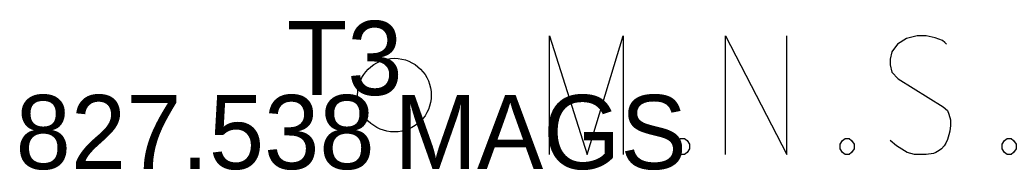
# Model space of a CAD drawing. Extents: x 1455931 to 1456172, y 560190 to 560355.
# Drawn here: x 1456075.1 to 1456088.52, y 560315.32 to 560317.35 of the extents above; entities that cross this region are included whole.
import ezdxf

# ---------------------------------------------------------------- set-up
doc = ezdxf.new("R2010")
doc.units = 0
for name, color, linetype in [('SV_P_Control_Cells_Set', 7, 'Continuous'), ('SV_X_Text_Comment', 7, 'Continuous'), ('SV_X_Text_Elevation', 7, 'Continuous'), ('SV_X_Text_Name', 7, 'Continuous')]:
    doc.layers.add(name, color=color, linetype=linetype)

msp = doc.modelspace()

# ---------------------------------------------------------------- linework, layer by layer
at = {"layer": 'SV_P_Control_Cells_Set'}
for points in [[(1456082.234, 560315.531), (1456082.234, 560317.131), (1456082.741, 560315.531), (1456083.226, 560317.131), (1456083.226, 560315.531)], [(1456084.604, 560315.531), (1456084.604, 560317.131), (1456085.431, 560315.531), (1456085.431, 560317.131)], [(1456087.581, 560317.018), (1456087.559, 560317.043), (1456087.525, 560317.068), (1456087.426, 560317.106), (1456087.305, 560317.131), (1456087.217, 560317.131), (1456087.184, 560317.131), (1456087.04, 560317.094), (1456086.919, 560317.018), (1456086.842, 560316.917), (1456086.82, 560316.816), (1456086.82, 560316.741), (1456086.842, 560316.64), (1456086.93, 560316.552), (1456087.537, 560316.174), (1456087.592, 560316.124), (1456087.614, 560316.073), (1456087.636, 560315.998), (1456087.636, 560315.922), (1456087.625, 560315.846), (1456087.614, 560315.796), (1456087.592, 560315.733), (1456087.57, 560315.683), (1456087.547, 560315.645), (1456087.514, 560315.607), (1456087.481, 560315.582), (1456087.437, 560315.557), (1456087.404, 560315.544), (1456087.305, 560315.531), (1456087.151, 560315.531), (1456087.052, 560315.557), (1456086.908, 560315.645), (1456086.82, 560315.72)], [(1456083.998, 560315.746), (1456084.053, 560315.746), (1456084.086, 560315.72), (1456084.119, 560315.67), (1456084.119, 560315.607), (1456084.086, 560315.557), (1456084.053, 560315.531), (1456083.998, 560315.531), (1456083.965, 560315.557), (1456083.932, 560315.607), (1456083.932, 560315.67), (1456083.965, 560315.72), (1456083.998, 560315.746)], [(1456086.214, 560315.746), (1456086.269, 560315.746), (1456086.302, 560315.72), (1456086.335, 560315.67), (1456086.335, 560315.607), (1456086.302, 560315.557), (1456086.269, 560315.531), (1456086.214, 560315.531), (1456086.181, 560315.557), (1456086.148, 560315.607), (1456086.148, 560315.67), (1456086.181, 560315.72), (1456086.214, 560315.746)], [(1456088.396, 560315.746), (1456088.451, 560315.746), (1456088.485, 560315.72), (1456088.517, 560315.67), (1456088.517, 560315.607), (1456088.485, 560315.557), (1456088.451, 560315.531), (1456088.396, 560315.531), (1456088.363, 560315.557), (1456088.33, 560315.607), (1456088.33, 560315.67), (1456088.363, 560315.72), (1456088.396, 560315.746)]]:
    msp.add_lwpolyline(points, dxfattribs=at)
msp.add_circle((1456080.145, 560316.331), 0.497, dxfattribs=at)

# ---------------------------------------------------------------- texts
at = {"layer": 'SV_X_Text_Comment'}
msp.add_text('MAGS', height=1, dxfattribs=at).set_placement((1456080.144, 560315.332))
at = {"layer": 'SV_X_Text_Elevation'}
msp.add_text('827.538', height=1, dxfattribs=at).set_placement((1456075.044, 560315.332))
at = {"layer": 'SV_X_Text_Name'}
msp.add_text('T3', height=1, dxfattribs=at).set_placement((1456078.694, 560316.332))

doc.saveas('drawing.dxf')
